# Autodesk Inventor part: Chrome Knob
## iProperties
Created: 2006-01
Part Number: Chrome Knob
Document SubType Name: Modeling
Designer: Martin
Material: Silver
Author: Martin
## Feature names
1. Extrusion1
2. Extrusion2
3. Fillet1
4. Hole1
5. Extrusion3
6. Fillet2
